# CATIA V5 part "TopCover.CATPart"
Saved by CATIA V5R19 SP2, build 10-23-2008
Part number: TopCover
Revision: ANY
Definition: UNKNOWN
Nomenclature: TopCover
Source: Unknown
Bounding box of the stored display mesh (mm): x -41.571 to 62, y -10 to 26.536, z -37.204 to 37.659
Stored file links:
  Z:\fausse table rondelle-20220905T211342Z-001\fausse table rondelle\TopCover.CATPart
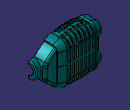
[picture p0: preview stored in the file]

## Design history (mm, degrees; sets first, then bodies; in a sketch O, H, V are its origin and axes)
AxisSystem1: origin (0, 0, 0), X (1, 0, 0), Y (0, 1, 0), Z (0, 0, 1)
Set1
  DatumSurface1 "NONE"
Set2 "FaceKO#NONE#22148"
  DatumSurface2 "Sur22148_1"
  DatumCurve1 "Crv22148_1"
  Line1 "Crv22148_2": stored without definition
  DatumCurve2 "Crv22148_3"
  Line2 "Crv22148_4": stored without definition
  Line3 "Crv22148_5": stored without definition
  DatumCurve3 "Crv22148_6"
  Line4 "Crv22148_7": stored without definition
  Line5 "Crv22148_8": stored without definition
  DatumCurve4 "Crv22148_9"
  Line6 "Crv22148_10": stored without definition
  Line7 "Crv22148_11": stored without definition
  DatumCurve5 "PCrv22148_12"
  Line8 "PCrv22148_13": stored without definition
  DatumCurve6 "PCrv22148_14"
  Line9 "PCrv22148_15": stored without definition
  Line10 "PCrv22148_16": stored without definition
Set3 "FaceKO#NONE#71171"
  DatumSurface3 "Sur71171_1"
  DatumCurve7 "Crv71171_1"
  DatumCurve8 "Crv71171_2"
  DatumCurve9 "Crv71171_3"
  DatumCurve10 "Crv71171_4"
  DatumCurve11 "PCrv71171_5"
Set4 "FaceKO#NONE#2572"
  DatumSurface4 "Sur2572_1"
  DatumCurve12 "Crv2572_1"
  Line11 "Crv2572_2": stored without definition
Set5 "FaceKO#NONE#3875"
  DatumSurface5 "Sur3875_1"
  DatumCurve13 "Crv3875_1"
  DatumCurve14 "Crv3875_2"
  DatumCurve15 "Crv3875_3"
Set6 "FaceKO#NONE#79686"
  DatumSurface6 "Sur79686_1"
  Line12 "Crv79686_1": stored without definition
  DatumCurve16 "Crv79686_2"
  Line13 "Crv79686_3": stored without definition
  DatumCurve17 "PCrv79686_4"
  DatumCurve18 "PCrv79686_5"
  DatumCurve19 "PCrv79686_6"
Body1 (main body)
